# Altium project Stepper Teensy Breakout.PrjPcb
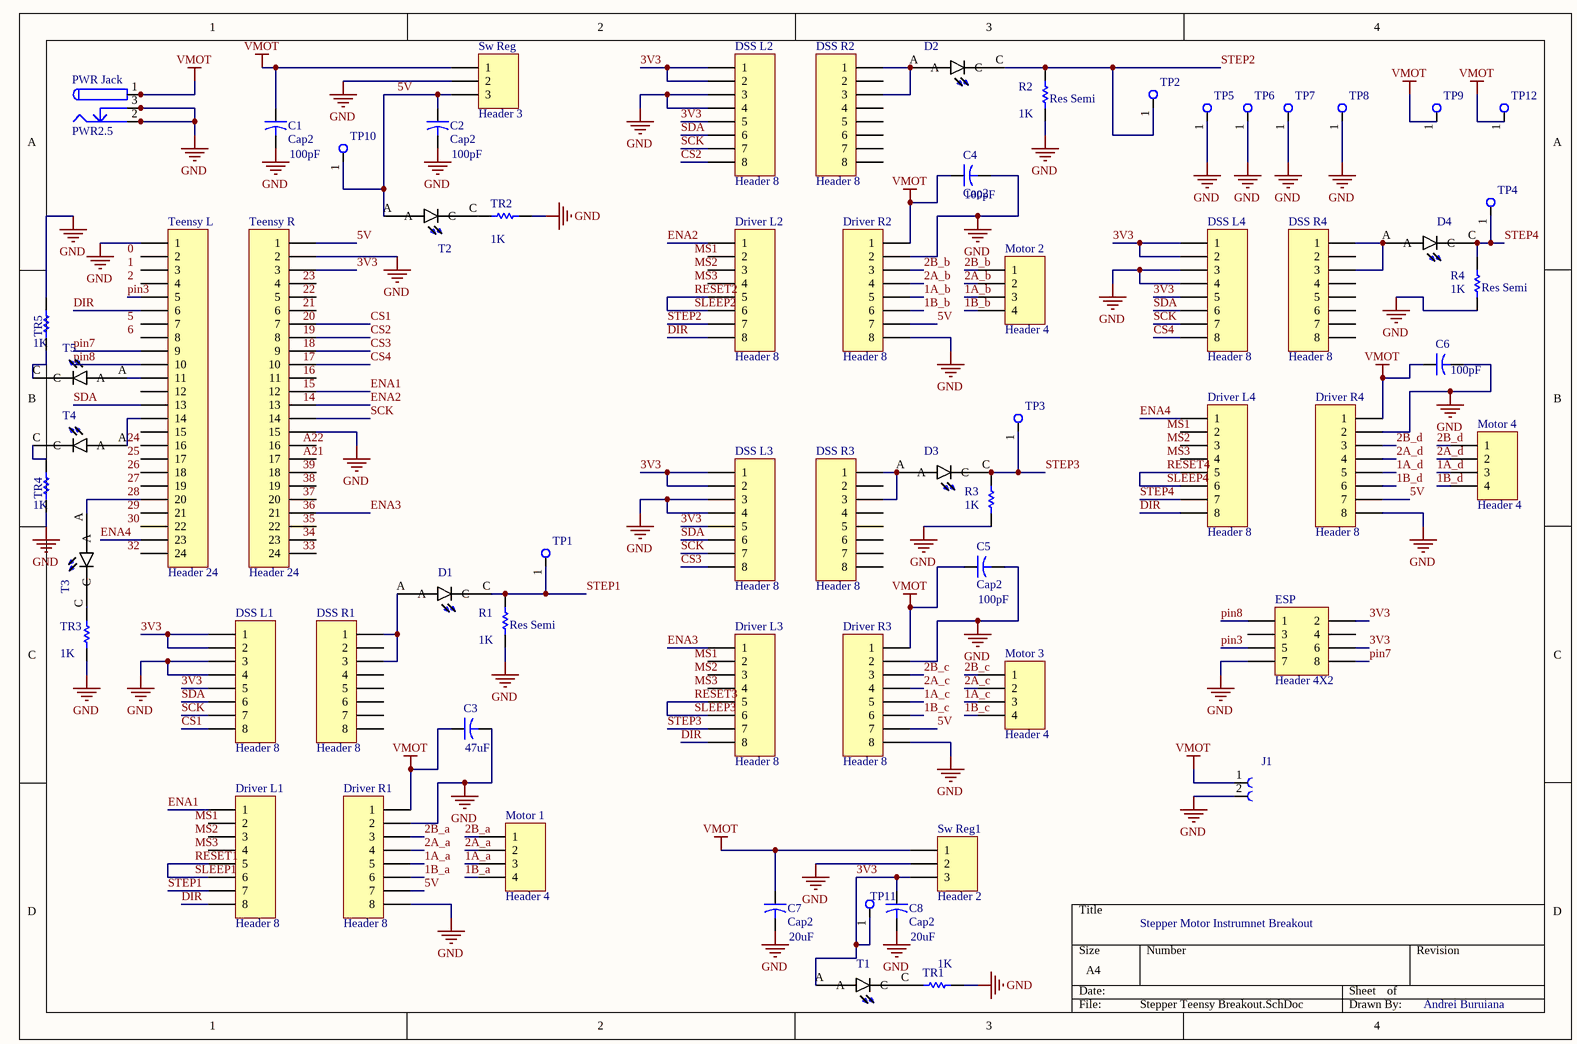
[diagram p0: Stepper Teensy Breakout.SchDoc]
1 sheet, 65 parts. Net scope: global (net labels, ports and power ports of the same name join across sheets).
Board file: Stepper Teensy Breakout.PcbDoc

## Sheet Stepper Teensy Breakout.SchDoc
size A4

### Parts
C1  Cap2  value 100pF  [CAPR5-4X5]
C2  Cap2  value 100pF  [CAPR5-4X5]
C3  value 47uF  [CAPR5-4X5]
C4  Cap2  value 100pF  [CAPR5-4X5]
C5  Cap2  value 100pF  [CAPR5-4X5]
C6  value 100pF  [CAPR5-4X5]
C7  Cap2  value 20uF  [CAPR5-4X5]
C8  Cap2  value 20uF  [CAPR5-4X5]
D1  LTL-1CHYE  [LED_LTL-1CHYE_LTL-1CHYE(Primary)]  (value not drawn)
D2  LTL-1CHYE  [LED_LTL-1CHYE_LTL-1CHYE(Primary)]  (value not drawn)
D3  LTL-1CHYE  [LED_LTL-1CHYE_LTL-1CHYE(Primary)]  (value not drawn)
D4  LTL-1CHYE  [LED_LTL-1CHYE_LTL-1CHYE(Primary)]  (value not drawn)
Driver_L1  Header 8  [HDR1X8]
Driver_L2  Header 8  [HDR1X8]
Driver_L3  Header 8  [HDR1X8]
Driver_L4  Header 8  [HDR1X8]
Driver_R1  Header 8  [HDR1X8]
Driver_R2  Header 8  [HDR1X8]
Driver_R3  Header 8  [HDR1X8]
Driver_R4  Header 8  [HDR1X8]
DSS_L1  Header 8  [HDR1X8]
DSS_L2  Header 8  [HDR1X8]
DSS_L3  Header 8  [HDR1X8]
DSS_L4  Header 8  [HDR1X8]
DSS_R1  Header 8  [HDR1X8]
DSS_R2  Header 8  [HDR1X8]
DSS_R3  Header 8  [HDR1X8]
DSS_R4  Header 8  [HDR1X8]
ESP  Header 4X2  [HDR2X4]
J1  (no value)  [691102710002]
Motor_1  Header 4  [HDR1X4]
Motor_2  Header 4  [HDR1X4]
Motor_3  Header 4  [HDR1X4]
Motor_4  Header 4  [HDR1X4]
PWR_Jack  PWR2.5  [KLD-0202]
R1  Res Semi  value 1K  [AXIAL-0.5]
R2  Res Semi  value 1K  [AXIAL-0.5]
R3  value 1K  [AXIAL-0.5]
R4  Res Semi  value 1K  [AXIAL-0.5]
Sw_Reg  Header 3  [HDR1X3]
Sw_Reg1  Header 2  [HDR1X3]
T1  LTL-1CHYE  [LED_LTL-1CHYE_LTL-1CHYE(Primary)]  (value not drawn)
T2  LTL-1CHYE  [LED_LTL-1CHYE_LTL-1CHYE(Primary)]  (value not drawn)
T3  LTL-1CHYE  [LED_LTL-1CHYE_LTL-1CHYE(Primary)]  (value not drawn)
T4  LTL-1CHYE  [LED_LTL-1CHYE_LTL-1CHYE(Primary)]  (value not drawn)
T5  LTL-1CHYE  [LED_LTL-1CHYE_LTL-1CHYE(Primary)]  (value not drawn)
Teensy_L  Header 24  [HDR1X24]
Teensy_R  Header 24  [HDR1X24]
TP1  (no value)  [TPCW51D250H460P]
TP2  (no value)  [TPCW51D250H460P]
TP3  (no value)  [TPCW51D250H460P]
TP4  (no value)  [TPCW51D250H460P]
TP5  (no value)  [TPCW51D250H460P]
TP6  (no value)  [TPCW51D250H460P]
TP7  (no value)  [TPCW51D250H460P]
TP8  (no value)  [TPCW51D250H460P]
TP9  (no value)  [TPCW51D250H460P]
TP10  (no value)  [TPCW51D250H460P]
TP11  (no value)  [TPCW51D250H460P]
TP12  (no value)  [TPCW51D250H460P]
TR1  value 1K  [AXIAL-0.5]
TR2  value 1K  [AXIAL-0.5]
TR3  value 1K  [AXIAL-0.5]
TR4  value 1K  [AXIAL-0.5]
TR5  value 1K  [AXIAL-0.5]

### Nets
GND: C1.2 C2.2 C3.2 C4.2 C5.2 C6.2 C7.2 C8.2 Driver_R1.2 Driver_R1.8 Driver_R2.2 Driver_R2.8 Driver_R3.2 Driver_R3.8 Driver_R4.2 Driver_R4.8 DSS_L1.3 DSS_L1.4 DSS_L2.3 DSS_L2.4 DSS_L3.3 DSS_L3.4 DSS_L4.3 DSS_L4.4 ESP.7 J1.2 PWR_Jack.2 PWR_Jack.2A PWR_Jack.2B PWR_Jack.3 PWR_Jack.3A PWR_Jack.3B R1.1 R2.1 R3.1 R4.1 Sw_Reg.2 Sw_Reg1.2 Teensy_L.1 Teensy_R.2 Teensy_R.15 TP5.1(TP) TP6.1(TP) TP7.1(TP) TP8.1(TP) TR1.1 TR2.1 TR3.1 TR4.1 TR5.2
VMOT: C1.1 C3.1 C4.1 C5.1 C6.1 C7.1 Driver_R1.1 Driver_R2.1 Driver_R3.1 Driver_R4.1 J1.1 PWR_Jack.1 PWR_Jack.1A PWR_Jack.1B Sw_Reg.1 Sw_Reg1.1 TP9.1(TP) TP12.1(TP)
1A_a: Driver_R1.5 Motor_1.3
1A_b: Driver_R2.5 Motor_2.3
1A_c: Driver_R3.5 Motor_3.3
1A_d: Driver_R4.5 Motor_4.3
1B_a: Driver_R1.6 Motor_1.4
1B_b: Driver_R2.6 Motor_2.4
1B_c: Driver_R3.6 Motor_3.4
1B_d: Driver_R4.6 Motor_4.4
2A_a: Driver_R1.4 Motor_1.2
2A_b: Driver_R2.4 Motor_2.2
2A_c: Driver_R3.4 Motor_3.2
2A_d: Driver_R4.4 Motor_4.2
2B_a: Driver_R1.3 Motor_1.1
2B_b: Driver_R2.3 Motor_2.1
2B_c: Driver_R3.3 Motor_3.1
2B_d: Driver_R4.3 Motor_4.1
3V3: C8.1 DSS_L1.1 DSS_L1.2 DSS_L1.5 DSS_L2.1 DSS_L2.2 DSS_L2.5 DSS_L3.1 DSS_L3.2 DSS_L3.5 DSS_L4.1 DSS_L4.2 DSS_L4.5 ESP.2 ESP.6 Sw_Reg1.3 T1.A Teensy_R.3 TP11.1(TP)
5V: C2.1 Driver_R1.7 Driver_R2.7 Driver_R3.7 Driver_R4.7 Sw_Reg.3 T2.A Teensy_R.1 TP10.1(TP)
24: T4.A Teensy_L.14
28: T3.A Teensy_L.20
CS1: DSS_L1.8 Teensy_R.7
CS2: DSS_L2.8 Teensy_R.8
CS3: DSS_L3.8 Teensy_R.9
CS4: DSS_L4.8 Teensy_R.10
DIR: Driver_L1.8 Driver_L2.8 Driver_L3.8 Driver_L4.8 Teensy_L.6
ENA1: Driver_L1.1 Teensy_R.12
ENA2: Driver_L2.1 Teensy_R.13
ENA3: Driver_L3.1 Teensy_R.21
ENA4: Driver_L4.1 Teensy_L.23
pin3: ESP.5 Teensy_L.5
pin7: ESP.8 Teensy_L.9
pin8: ESP.1 Teensy_L.10
RESET1: Driver_L1.5 Driver_L1.6  [also labelled SLEEP1]
RESET2: Driver_L2.5 Driver_L2.6  [also labelled SLEEP2]
RESET3: Driver_L3.5 Driver_L3.6  [also labelled SLEEP3]
RESET4: Driver_L4.5 Driver_L4.6  [also labelled SLEEP4]
SCK: DSS_L1.7 DSS_L2.7 DSS_L3.7 DSS_L4.7 Teensy_R.14
SDA: DSS_L1.6 DSS_L2.6 DSS_L3.6 DSS_L4.6 Teensy_L.13
STEP1: D1.C Driver_L1.7 R1.2 TP1.1(TP)
STEP2: D2.C Driver_L2.7 R2.2 TP2.1(TP)
STEP3: D3.C Driver_L3.7 R3.2 TP3.1(TP)
STEP4: D4.C Driver_L4.7 R4.2 TP4.1(TP)
NetD1_A: D1.A DSS_R1.1 DSS_R1.3
NetD2_A: D2.A DSS_R2.1 DSS_R2.3
NetD3_A: D3.A DSS_R3.1 DSS_R3.3
NetD4_A: D4.A DSS_R4.1 DSS_R4.3
NetT1_C: T1.C TR1.2
NetT2_C: T2.C TR2.2
NetT3_C: T3.C TR3.2
NetT4_C: T4.C TR4.2
NetT5_A: T5.A Teensy_L.11
NetT5_C: T5.C TR5.1

Not connected (* = marked no-connect by the designer): Driver_L1 2 3 4; Driver_L2 2 3 4; Driver_L3 2 3 4; Driver_L4 2 3 4; DSS_R1 2 4 5 6 7 8; DSS_R2 2 4 5 6 7 8; DSS_R3 2 4 5 6 7 8; DSS_R4 2 4 5 6 7 8; ESP 3 4; Teensy_L 2 3 4 7 8 12 15 16 17 18 19 21 22 24; Teensy_R 4 5 6 11 16 17 18 19 20 22 23 24

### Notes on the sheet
- Stepper Motor Instrumnet Breakout
- Andrei Buruiana
- Labels drawn without touching a wire or pin: 0, 1, 2, 5, 6, 14, 15, 16, 17, 18, 19, 20, 21, 22, 23, 25, 26, 27, 29, 30, 32, 33, 34, 35, 36, 37, 38, 39, A21, A22, MS1, MS2, MS3

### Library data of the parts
C1-C8 = Cap2: Capacitor
D1-D4 T1-T5 = LTL-1CHYE: Yellow 3.1 mm 45Â° Tinted Clear 40 mcd 2.1 V LED Through Hole; MF: Lite-On
Driver_L1-Driver_L4 Driver_R1-Driver_R4 DSS_L1-DSS_L4 DSS_R1-DSS_R4 = Header 8: Header, 8-Pin
ESP = Header 4X2: Header, 4-Pin, Dual row
J1 = 691102710002: 102 Series 5mm Pitch Straight, PCB Terminal Block, Through Hole, 2 Way; MF: Wurth Electronics
Motor_1-Motor_4 = Header 4: Header, 4-Pin
PWR_Jack = PWR2.5: Low Voltage Power Supply Connector
R1-R4 TR1-TR5 = Res Semi: Semiconductor Resistor
Sw_Reg Sw_Reg1 = Header 3: Header, 3-Pin
Teensy_L Teensy_R = Header 24: Header, 24-Pin
TP1-TP12 = 5003: Test Point; Orange; Thru-Hole; Snap-Fit; SilverPlate; 0.040 in. Dia.; 0.300 In.; MF: Keystone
